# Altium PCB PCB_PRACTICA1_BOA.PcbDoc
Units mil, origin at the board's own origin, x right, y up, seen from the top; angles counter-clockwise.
Board outline 1614.17 x 1614.17 mil, 2 copper layers (Top Layer, Bottom Layer); 25 components, 36 nets, 93 pads, 3 vias.
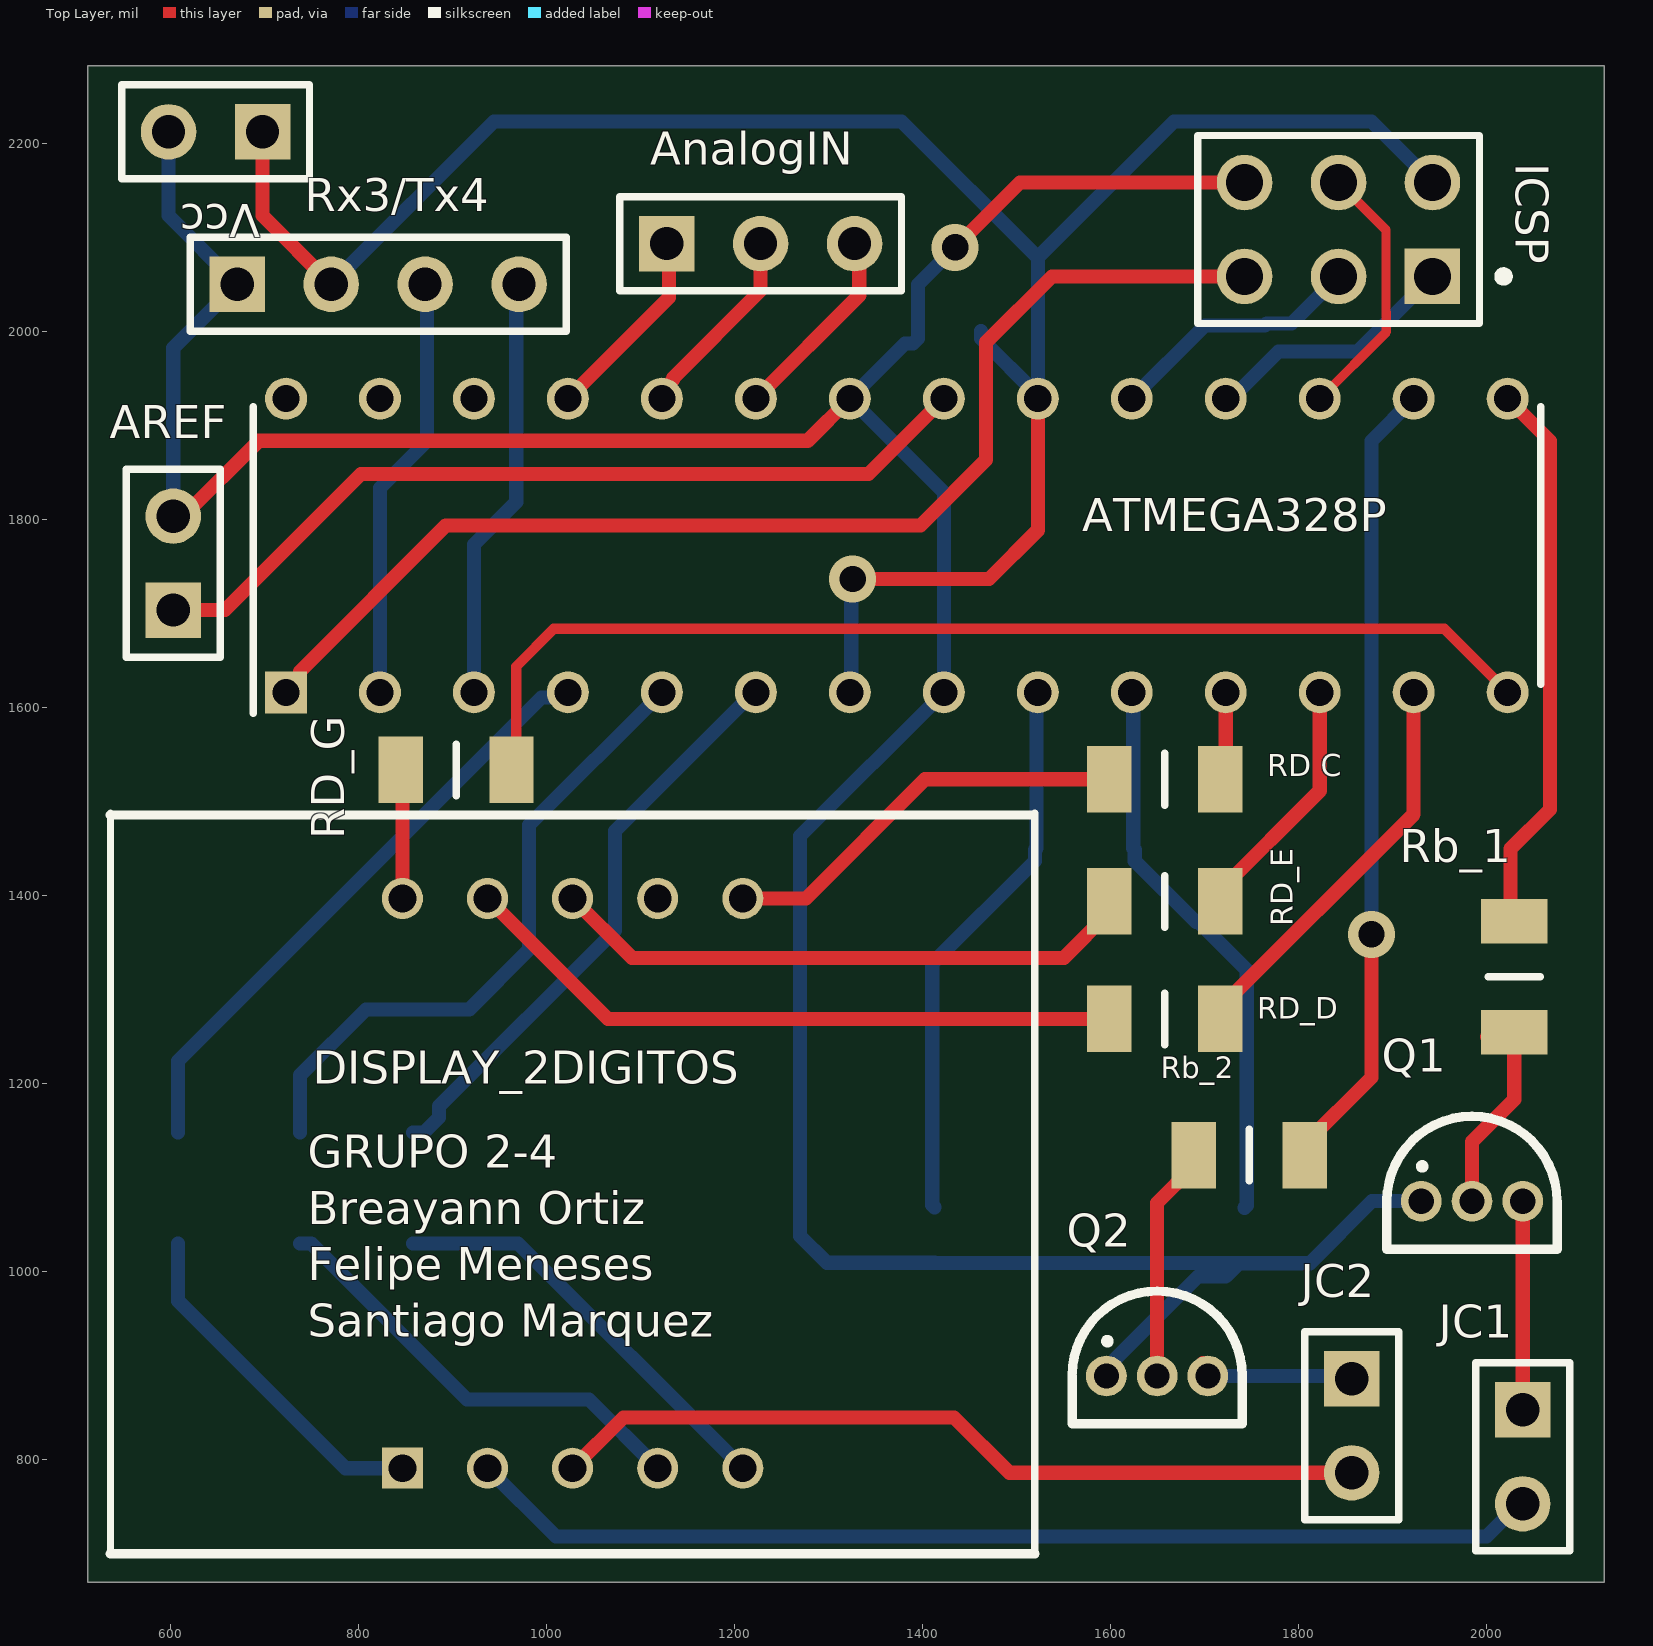
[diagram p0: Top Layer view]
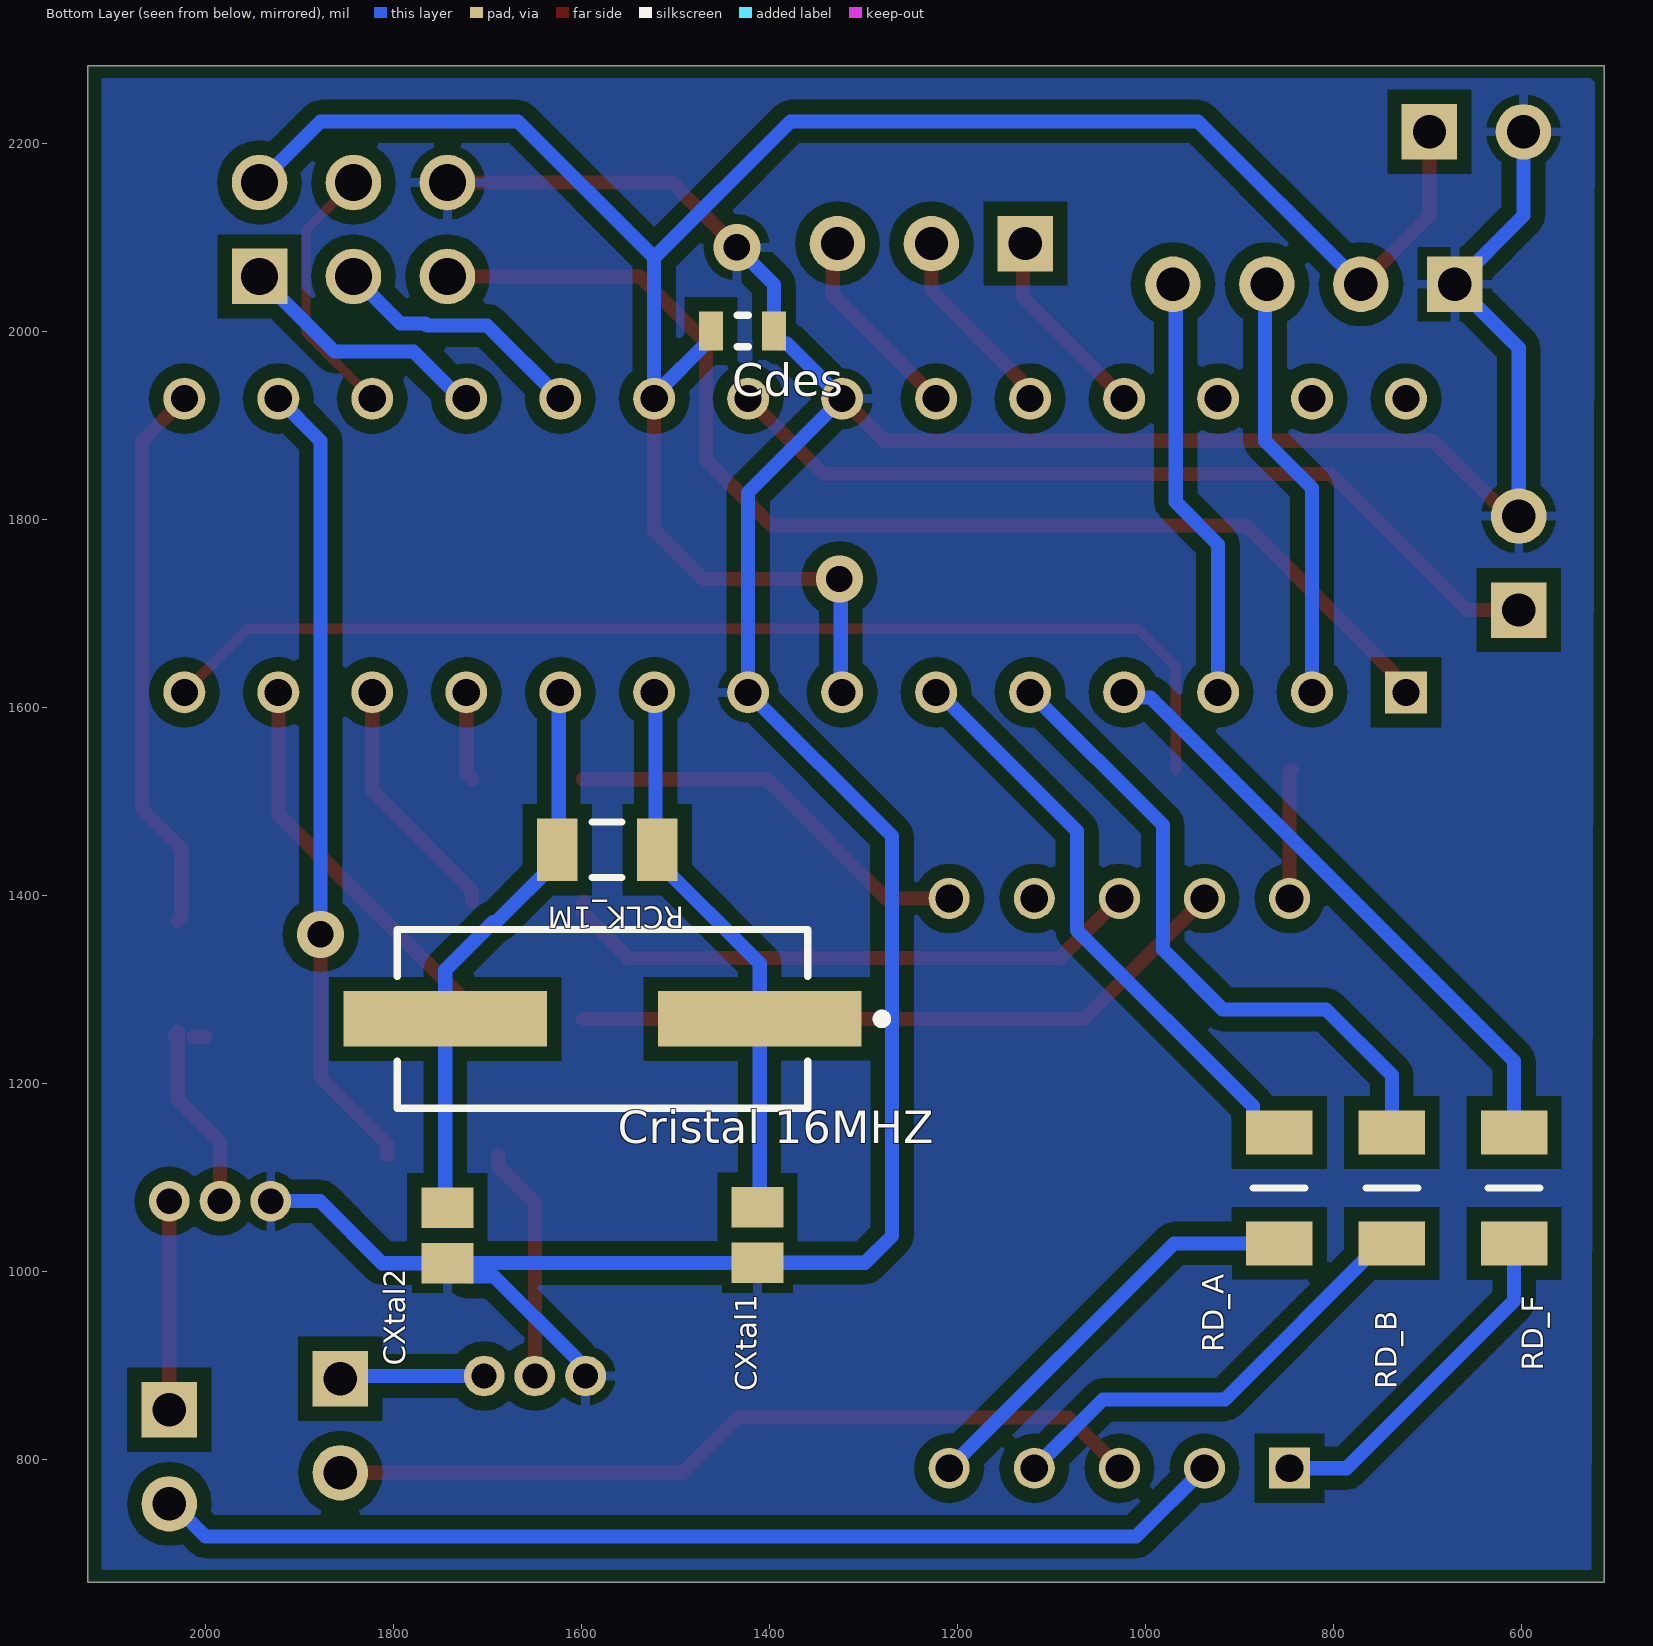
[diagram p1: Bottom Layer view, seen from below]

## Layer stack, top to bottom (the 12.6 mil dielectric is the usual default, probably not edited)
Top Solder: solder mask 0.4, Solder Resist, Dk 3.5
Top Layer: signal copper 1.4
Dielectric 1: dielectric 12.6, FR-4, Dk 4.8
Bottom Layer: signal copper 1.4
Bottom Solder: solder mask 0.4, Solder Resist, Dk 3.5

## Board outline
511.81,669.29 511.81,2283.46 2125.98,2283.46 2125.98,669.29

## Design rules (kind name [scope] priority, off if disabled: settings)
Clearance [All] p1: gap=15 ignorepadtopadclearanceinfootprint=FALSE except(0: Arc-Hole Track-Hole SMDPad-Hole THPad-Hole Via-Hole Fill-Hole Poly-Hole Region-Hole Text-Hole; 10: THPad-THPad)
HoleSize [All] p1: absolutevalues=TRUE maxlimit=98.43 minlimit=15.75 maxpercent=80.000 minpercent=20.000
MinimumAnnularRing [All] p1: minimumring=10
PolygonConnect [All] p1: connectstyle=Relief reliefconductorwidth=10 reliefentries=4 polygonreliefangle="90 Angle" airgapwidth=10
RoutingVias [All] p1: holewidth=28 width=50 viastyle="Through Hole" minholewidth=28 minwidth=50 maxholewidth=28 maxwidth=50
SolderMaskExpansion [All] p1: expansion=4 istentingtop=FALSE
UnRoutedNet [All] p1: checkbadconnections=TRUE
Width [All] p1: maxlimit=20 minlimit=10 preferedwidth=15 minimp=50.000000 maximp=50.000000 favimp=50.000000
28 further rules are at their usual default settings.

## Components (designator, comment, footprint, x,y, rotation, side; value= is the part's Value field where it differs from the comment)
AnalogIN "Header 3" HDR1X3 1128,2094 r0 top
AREF "VCC" HDR1X2 603,1704 r90 top
ATMEGA328P "ATMEGA328P-PU" DIP794W53P254L3467H457Q28N 1373,1772.74 r90 top
Cdes "CGA3E3X7S2A104K080AB" CAPC1608X90X20ML10 1429,2001 r0 bottom
"Cristal 16MHZ" "ATS16ASM-1" CTS-ATS-SM-XTAL-2 1578,1269 r0 bottom (schematic designator Cristal_16MHZ)
CXtal1 "Cap" C0805 1413,1039 r90 bottom value=22pF
CXtal2 "Cap" C0805 1743,1038.53 r90 bottom value=22pF
DISPLAY_2DIGITOS "HDSP-A103" DIP508W51P254L1270H609Q10N 1028,1094 r90 top
ICSP "M20-9980346" HRWN-M20-9980346_V 1843,2109 r180 top
JC1 "Header 2" HDR1X2 2039,853 r270 top
JC2 "Header 2" HDR1X2 1857,886 r270 top
Q1 "2N2222A" TO-18_4 1985,1075 r270 top
Q2 "2N2222A" TO-18_4 1650,889 r270 top
Rb_1 "CR1206-FX-2200ELF" RESC3216X75N 2030,1314 r90 top
Rb_2 "CR1206-FX-2200ELF" RESC3216X75N 1748,1124 r0 top
RCLK_1M "Res1" C1206 1573,1449 r180 bottom value=1M
"RD C" "CR1206-FX-2200ELF" RESC3216X75N 1658,1524 r0 top (schematic designator RD_C)
RD_A "CR1206-FX-2200ELF" RESC3216X75N 858,1089 r90 bottom
RD_B "CR1206-FX-2200ELF" RESC3216X75N 738,1089 r90 bottom
RD_D "CR1206-FX-2200ELF" RESC3216X75N 1658,1269 r0 top
RD_E "CR1206-FX-2200ELF" RESC3216X75N 1658,1394 r0 top
RD_F "CR1206-FX-2200ELF" RESC3216X75N 608,1089 r90 bottom
RD_G "CR1206-FX-2200ELF" RESC3216X75N 903.94,1534 r0 top
Rx3/Tx4 "Header 4" HDR1X4 671,2050.74 r0 top
Vcc "Header 2" HDR1X2 698,2213 r180 top

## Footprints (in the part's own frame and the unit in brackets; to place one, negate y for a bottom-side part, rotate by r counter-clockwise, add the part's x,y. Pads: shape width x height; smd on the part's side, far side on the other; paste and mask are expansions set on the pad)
C0805 [mm] "Chip Capacitor, Body 2.0x1.3mm, IPC High Density"
  rect 1.1x1.4 smd: 1(-0.75,0) 2(0.75,0)
  body extent -1.1,-0.72 1.1,0.72, height 1.4
C1206 [mm] "Chip Capacitor, Body 3.2x1.6mm, IPC High Density"
  rect 1.1x1.7 smd: 1(-1.35,0) 2(1.35,0)
  silkscreen extent -0.4,-0.75 0.4,0.75, body extent -1.7,-0.9 1.7,0.9, height 1.3
CAPC1608X90X20ML10 [mm] "Chip Capacitor, 2-Leads, Body 1.70x0.90mm, IPC Low Density"
  rect 0.65x1.05 smd: 1(-0.85,0) 2(0.85,0)
  silkscreen extent -0.15,-0.43 0.15,0.43, body extent -0.85,-0.45 0.85,0.45, height 0.9
CTS-ATS-SM-XTAL-2 [mm] "SMD, 2-Leads, Body 11.1x4.83mm, Pitch 8.5mm"
  rect 5.5x1.5 smd: 1(-4.25,0) 2(4.25,0)
  silkscreen extent -7.67,-2.41 5.55,2.41, body extent -5.59,-2.42 5.59,2.42, height 4.3
DIP508W51P254L1270H609Q10N [mm]
  rect 1.108x1.108 hole 0.75: 1(-7.7,4.6)
  round 1.108 hole 0.75: 2(-7.7,2.3) 3(-7.7,0.003) 4(-7.7,-2.3) 5(-7.7,-4.6) 6(7.7,-4.6) 7(7.7,-2.3) 8(7.7,0.003) 9(7.7,2.3) 10(7.7,4.6)
  silkscreen extent -10.01,-12.5 10,12.5
DIP794W53P254L3467H457Q28N [mil]
  rect 44.61x44.61 hole 28.86: 1(-156.26,650)
  round 44.61 hole 28.86: 2(-156.26,550) 3(-156.26,450) 4(-156.26,350) 5(-156.26,250) 6(-156.26,150) 7(-156.26,50) 8(-156.26,-50) 9(-156.26,-150) 10(-156.26,-250) 11(-156.26,-350) 12(-156.26,-450) 13(-156.26,-550) 14(-156.26,-650) 15(156.26,-650) 16(156.26,-550) 17(156.26,-450) 18(156.26,-350) 19(156.26,-250) 20(156.26,-150) 21(156.26,-50) 22(156.26,50) 23(156.26,150) 24(156.26,250) 25(156.26,350) 26(156.26,450) 27(156.26,550) 28(156.26,650)
  silkscreen extent -179,-685 147,685, body extent -161,-682 161,683, height 180
HDR1X2 [mm] "Connector; Header; 2 Position"
  rect 1.5x1.5 hole 0.9: 1(0,0)
  round 1.5 hole 0.9: 2(2.54,0)
  silkscreen extent -1.27,-1.27 3.81,1.27
HDR1X3 [mm] "Connector; Header; 3 Position"
  rect 1.5x1.5 hole 0.9: 1(0,0)
  round 1.5 hole 0.9: 2(2.54,0) 3(5.08,0)
  silkscreen extent -1.27,-1.27 6.35,1.27
HDR1X4 [mm] "Connector; Header; 4 Position"
  rect 1.5x1.5 hole 0.9: 1(0,0)
  round 1.5 hole 0.9: 2(2.54,0) 3(5.08,0) 4(7.62,0)
  silkscreen extent -1.27,-1.27 8.89,1.27
HRWN-M20-9980346_V [mm] "THD, 6-Leads, Body 7.62x5.08mm, Pitch 2.54mm"
  rect 1.5x1.5 hole 1: 1(-2.54,1.27)
  round 1.5 hole 1: 2(-2.54,-1.27) 3(0,1.27) 4(0,-1.27) 5(2.54,1.27) 6(2.54,-1.27)
  silkscreen extent -4.59,-2.54 3.81,2.54, body extent -3.81,-2.54 3.81,2.54, height 8.64
RESC3216X75N [mm]
  rect 1.2x1.8 smd: 1(-1.5,0) 2(1.5,0)
  silkscreen extent 0,-0.7 0,0.7, body extent -1.6,-0.8 1.6,0.8, height 0.75
TO-18_4 [mm]
  round 1.1 hole 0.68: 1(0,-1.372) 2(0,0) 3(0,1.372)
  silkscreen extent -2.3,-2.3 1.3,2.3

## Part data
AnalogIN: "Header, 3-Pin", Supplier Part Number 1=WM50016-03-ND
AREF: library part "Header 2", "Header, 2-Pin", Supplier Part Number 1=WM4111-ND
ATMEGA328P: "Integrated Circuit", Manufacturer_Name=Microchip, Mouser Part Number=556-ATMEGA328P-PU, RS Part Number=9222142P, Supplier Part Number 1=ATMEGA328P-PU-ND
Cdes: library part CMP-2000-04983-1, "Chip Capacitor, 100 nF, +/- 10%, 100 V, -55 to 125 degC, 0603 (1608 Metric), RoHS, Tape and Reel", Capacitance=0.1µF, Manufacturer=TDK, Operating Temperature=-55degC~125degC, Package / Case=0603(1608Metric), Package Description="2-Pin Surface Mount Device, Body 1.6 x 0.8 mm", Package Reference=603, PCN Part Number=MLCCPartNumberChange30/Nov/2012, Ratings=AEC-Q200, Standard Package=1, Temperature Coefficient=X7S, Tolerance=±10%, Voltage - Rated=100V
"Cristal 16MHZ": library part CMP-0585-00002-2, "ATS-SM Series Quartz Crystal, 16 MHz, -20 to 70 degC, 11.1 x 4.83 x 4.3mm SMD, RoHS, Tape and Reel", Frequency="16 MHz", Manufacturer="CTS Corporation", Operating Temperature="-20 to 70 degC", Shunt Capacitance (C0)="7.0 pF Max"
CXtal1 CXtal2: "Capacitor", Supplier Part Number 1=399-1091-1-ND
DISPLAY_2DIGITOS: "Display", Manufacturer_Name="Avago Technologies", Mouser Part Number=630-HDSP-A103, RS Part Number=4356739
ICSP: library part CMP-2000-06636-1, "Male Header, Pitch 2.54 mm, 2 x 3 Position, Height 8.64 mm, Tail Length 3 mm, -40 to 105 degC, RoHS, Bulk", Color=Black, Manufacturer=Harwin-Inc., Package Description="Male Header, Pitch 2.54 mm, 2 x 3 Position, Height 8.64 mm, Tail Length 3 mm"
JC1 JC2 Vcc: "Header, 2-Pin"
Q1 Q2: "Transistor BJT NPN", Manufacturer_Name="Microsemi Corporation", Mouser Part Number=494-2N2222A
Rb_1 Rb_2 "RD C" RD_A RD_B RD_D RD_E RD_F RD_G: "Resistor", Manufacturer_Name=Bourns, Mouser Part Number=652-CR1206FX-2200ELF, Supplier Part Number 1=CR1206-FX-2200ELFCT-ND
RCLK_1M: "Resistor"
Rx3/Tx4: "Header, 4-Pin", Supplier Part Number 1=732-5365-5-ND

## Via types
v1: diameter 50, hole 28, Top Layer to Bottom Layer, 3 vias

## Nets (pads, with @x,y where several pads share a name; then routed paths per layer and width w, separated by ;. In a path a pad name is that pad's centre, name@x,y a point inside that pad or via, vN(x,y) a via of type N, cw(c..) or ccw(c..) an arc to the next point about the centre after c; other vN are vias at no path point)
GND: AREF.2 ATMEGA328P.8 ATMEGA328P.22 Cdes.1 CXtal1.1 CXtal2.1 ICSP.6 Q1.1 Q2.1 Rx3/Tx4.1 Vcc.2 | length 3686.3
  Top Layer w15: AREF.2 614,1804 694.2,1884.2 1278.2,1884.2 ATMEGA328P.22 ; v1(1435,2090) 1504,2159 ICSP.6
  Bottom Layer w15: Vcc.2@598,2219 598,2123.74 Rx3/Tx4.1 603,1982.74 AREF.2 ; v1(1435,2090) 1395.54,2050.54 Cdes.1 1395.54,1993.13 1390.24,1987.83 1381.83,1987.83 ATMEGA328P.22 1423,1829 ATMEGA328P.8 1270,1463.48 1270,1038 1298.53,1009.47 CXtal1.1 1413.24,1009.24 CXtal2.1@1737.33,1009.24 ; Q2.1 1596,896.66 1605.85,906.51 1605.85,907.29 1693.4,994.85 1722.94,994.85 CXtal2.1@1737.33,1009.24 ; Q1.1 1878.62,1075 1812.62,1009 CXtal2.1 1737.57,1009 CXtal2.1@1737.33,1009.24
NetAnalogIN_1: AnalogIN.1 ATMEGA328P.25 | length 209.5
  Top Layer w15: ATMEGA328P.25 1130.5,2036.5 AnalogIN.1@1130.5,2094
NetAnalogIN_2: AnalogIN.2 ATMEGA328P.24 | length 208.5
  Top Layer w15: ATMEGA328P.24 1123,1937.01 1134.68,1948.69 1134.68,1950.68 1228,2044 AnalogIN.2
NetAnalogIN_3: AnalogIN.3 ATMEGA328P.23 | length 210.6
  Top Layer w15: ATMEGA328P.23 1333,2039 AnalogIN.3@1333,2094
NetAREF_1: AREF.1 ATMEGA328P.21 | length 913.2
  Top Layer w15: AREF.1 658,1704 803,1849 1343,1849 ATMEGA328P.21
NetATMEGA328P_1: ATMEGA328P.1 ICSP.5 | length 1280.9
  Top Layer w15: ATMEGA328P.1 737.8,1631.28 737.8,1638.8 893,1794 1398,1794 1468,1864 1468,1989 1538,2059 ICSP.5
NetATMEGA328P_2: ATMEGA328P.2 Rx3/Tx4.3 | length 455.8
  Bottom Layer w15: ATMEGA328P.2 823,1834 873,1884 873,2048.74 Rx3/Tx4.3
NetATMEGA328P_3: ATMEGA328P.3 Rx3/Tx4.4 | length 454.1
  Bottom Layer w15: ATMEGA328P.3 923,1774 968,1819 968,2047.74 Rx3/Tx4.4
NetATMEGA328P_4: ATMEGA328P.4 RD_F.2 | length 653.5
  Bottom Layer w15: RD_F.2 608,1224 994.82,1610.82 1017.34,1610.82 ATMEGA328P.4
NetATMEGA328P_5: ATMEGA328P.5 RD_B.2 | length 692.3
  Bottom Layer w15: RD_B.2 738,1209 808,1279 918,1279 981.76,1342.76 981.76,1475.24 ATMEGA328P.5
NetATMEGA328P_6: ATMEGA328P.6 RD_A.2 | length 628
  Bottom Layer w15: RD_A.2 869.81,1148.06 885.93,1164.18 885.93,1175.99 1073,1363.06 1073,1469 1220.48,1616.48 ATMEGA328P.6
NetATMEGA328P_9: "Cristal 16MHZ.1" ATMEGA328P.9 CXtal1.2 RCLK_1M.2 | length 595.4
  Bottom Layer w15: CXtal1.2 1410.68,1070.85 1410.68,1269 1410.68,1328.02 1519.85,1437.19 RCLK_1M.2 1521.43,1450.57 1521.43,1614.91 ATMEGA328P.9
NetATMEGA328P_10: "Cristal 16MHZ.2" ATMEGA328P.10 CXtal2.2 RCLK_1M.1 | length 601.8
  Bottom Layer w15: ATMEGA328P.10 1624.57,1614.91 1624.57,1450.57 RCLK_1M.1 1626.15,1437.19 1691.31,1372.03 1694.32,1372.03 1745.32,1321.03 1745.32,1269 1745.32,1070.38 CXtal2.2
NetATMEGA328P_11: "RD C.2" ATMEGA328P.11 | length 94.9
  Top Layer w15: 1717.06,1524 1723,1529.94 ATMEGA328P.11
NetATMEGA328P_12: ATMEGA328P.12 RD_E.2 | length 266.4
  Top Layer w15: RD_E.2 1717.06,1405.81 1823,1511.76 ATMEGA328P.12
NetATMEGA328P_13: ATMEGA328P.13 RD_D.2 | length 432.8
  Top Layer w15: RD_D.2 1717.06,1280.81 1923,1486.76 ATMEGA328P.13
NetATMEGA328P_14: ATMEGA328P.14 RD_G.2 | length 1209.5
  Top Layer w11: RD_G.2@968,1534 968,1644 1008,1684 1955.48,1684 ATMEGA328P.14
NetATMEGA328P_15: ATMEGA328P.15 Rb_1.2 | length 593.6
  Top Layer w15: ATMEGA328P.15 2068,1884 2068,1492 2026,1450 2026,1377.06 Rb_1.2
NetATMEGA328P_16: ATMEGA328P.16 Rb_2.2 | length 853
  Top Layer w15: Rb_2.2 1807.06,1135.81 1878,1206.76 v1(1878,1359)
  Bottom Layer w15: v1(1878,1359) 1878,1884 ATMEGA328P.16
NetATMEGA328P_17: ATMEGA328P.17 ICSP.4 | length 280.5
  Top Layer w10: ATMEGA328P.17 1894,2000 1894,2020.66 1893.47,2021.19 1893.47,2108.53 ICSP.4
NetATMEGA328P_18: ATMEGA328P.18 ICSP.1 | length 281.9
  Bottom Layer w15: ATMEGA328P.18@1728.66,1934.66 ATMEGA328P.18 1729,1929 1779,1979 1863,1979 ICSP.1
NetATMEGA328P_19: ATMEGA328P.19 ICSP.3 | length 273.8
  Bottom Layer w15: ATMEGA328P.19 1700.97,2006.97 1764.55,2006.97 1766.58,2009 1793,2009 ICSP.3
NetDISPLAY_2DIGITOS_1: DISPLAY_2DIGITOS.1 RD_F.1 | length 373.6
  Bottom Layer w15: RD_F.1 608,969 786.15,790.85 DISPLAY_2DIGITOS.1
NetDISPLAY_2DIGITOS_2: DISPLAY_2DIGITOS.2 JC1.2 | length 1146.2
  Bottom Layer w15: DISPLAY_2DIGITOS.2 1010.3,718 2000.42,718 2035.42,753 JC1.2
NetDISPLAY_2DIGITOS_3: DISPLAY_2DIGITOS.3 JC2.2 | length 878.9
  Top Layer w15: DISPLAY_2DIGITOS.3@1027.88,787.9 DISPLAY_2DIGITOS.3 1082.03,845 1434,845 1493,786 JC2.2
NetDISPLAY_2DIGITOS_4: DISPLAY_2DIGITOS.4 RD_B.1 | length 479.6
  Bottom Layer w15: RD_B.1 749.81,1029.94 915.76,864 1045.4,864 DISPLAY_2DIGITOS.4
NetDISPLAY_2DIGITOS_5: DISPLAY_2DIGITOS.5 RD_A.1 | length 450.1
  Bottom Layer w15: RD_A.1 970.01,1029.94 DISPLAY_2DIGITOS.5
NetDISPLAY_2DIGITOS_6: "RD C.1" DISPLAY_2DIGITOS.6 | length 442.4
  Top Layer w15: DISPLAY_2DIGITOS.6 1276.15,1397.15 1403,1524 1598.94,1524
NetDISPLAY_2DIGITOS_8: DISPLAY_2DIGITOS.8 RD_E.1 | length 629
  Top Layer w15: DISPLAY_2DIGITOS.8 1091.03,1334 1550.76,1334 1598.94,1382.19 RD_E.1
NetDISPLAY_2DIGITOS_9: DISPLAY_2DIGITOS.9 RD_D.1 | length 714.6
  Top Layer w15: DISPLAY_2DIGITOS.9 1065.6,1269 RD_D.1
NetDISPLAY_2DIGITOS_10: DISPLAY_2DIGITOS.10 RD_G.1 | length 137.7
  Top Layer w15: RD_G.1 846.9,1531.99 DISPLAY_2DIGITOS.10
NetJC1_1: JC1.1 Q1.3 | length 222
  Top Layer w15: JC1.1 Q1.3
NetJC2_1: JC2.1 Q2.3 | length 170.3
  Top Layer w15: Q2.3@1698.58,902.86 1698.58,894.42 Q2.3
  Bottom Layer w15: Q2.3 1854,889 JC2.1
NetQ1_2: Q1.2 Rb_1.1 | length 214.6
  Top Layer w15: Q1.2 1985,1138.24 2030,1183.24 Rb_1.1 Rb_1.1@2033,1251.94 ; Rb_1.1@2001.19,1249.94 Rb_1.1@2013,1249.94
NetQ2_2: Q2.2 Rb_2.1 | length 251.1
  Top Layer w15: Q2.2 1650,1073.24 1688.94,1112.19 Rb_2.1
VCC: ATMEGA328P.7 ATMEGA328P.20 Cdes.2 ICSP.2 Rx3/Tx4.2 Vcc.1 | length 2321.1
  Top Layer w15: Vcc.1@698,2219 698,2123.74 Rx3/Tx4.2 ; v1(1326,1737) 1471,1737 1523,1789 ATMEGA328P.20
  Bottom Layer w15: Rx3/Tx4.2 944.26,2224 1378,2224 1523,2079 ; ATMEGA328P.7 1324.5,1617.98 1324.5,1735.5 v1(1326,1737) ; Cdes.2 1462.46,1993.13 ATMEGA328P.20@1523,1932.59 ; ATMEGA328P.20@1517.34,1923.34 ATMEGA328P.20 ATMEGA328P.20@1523,1932.59 ; ICSP.2 1878,2224 1668,2224 1523,2079 ; ATMEGA328P.20@1523,1932.59 1523,2079
pads on no net: ATMEGA328P.26 ATMEGA328P.27 ATMEGA328P.28 DISPLAY_2DIGITOS.7

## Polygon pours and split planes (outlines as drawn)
no net on Top Layer "NONET_L01_P003" (solid, pour order 3): 520.28,2275
GND on Bottom Layer "GND_L02_P005" (solid, pour order 5): 522,2272 524,2270 2111,2270 2111,684 2110,683 526,683

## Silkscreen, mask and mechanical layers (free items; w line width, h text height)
Top Overlay:
  text "GRUPO 2-4 / Breayann Ortiz / Felipe Meneses / Santiago Marquez" at 746,919 h60
Mechanical 1:
  the board outline again, w10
